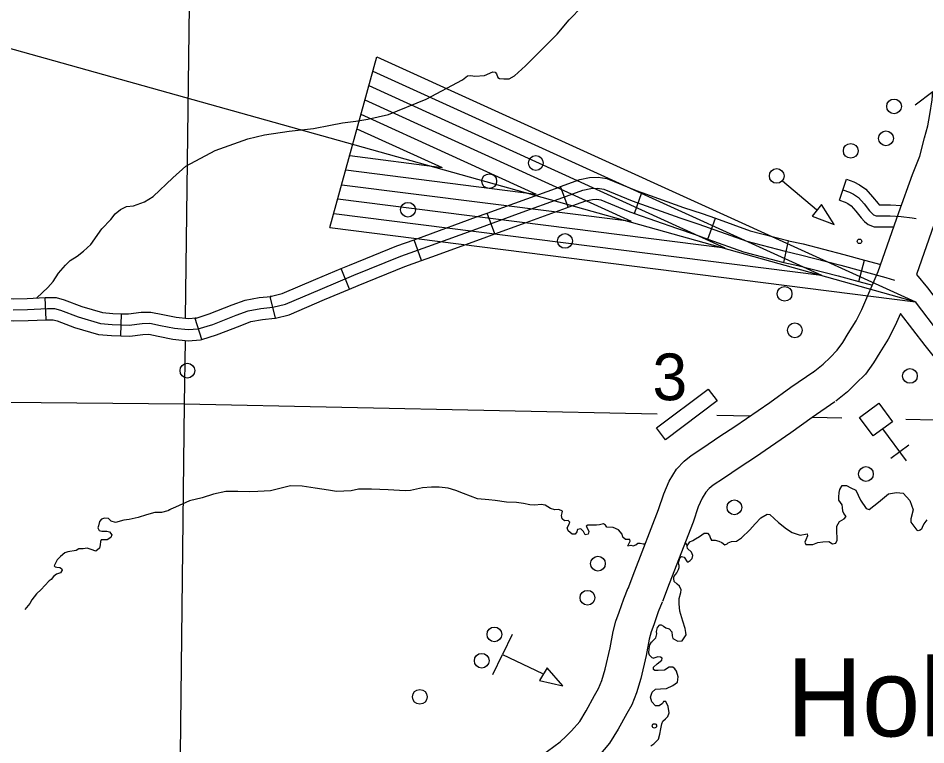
# Model space of a CAD drawing. Extents: x 1369979 to 1371646, y 379997 to 381064.
# Drawn here: x 1370658.6 to 1370730.7, y 380459 to 380516.7 of the extents above; entities that cross this region are included whole.
import ezdxf

# ---------------------------------------------------------------- set-up
doc = ezdxf.new("R2010")
doc.units = 0
for name, color, linetype in [('Default', 7, 'Continuous'), ('R_Border Notes', 7, 'Continuous'), ('R_Draft', 7, 'Continuous')]:
    doc.layers.add(name, color=color, linetype=linetype)

msp = doc.modelspace()

# ---------------------------------------------------------------- linework, layer by layer
at = {"layer": 'Default'}
for p, q in [((1370478.05, 380564.69), (1370729.894, 380494.17)), ((1370683.39, 380500.064), (1370687.104, 380513.627)), ((1370687.104, 380513.627), (1370729.871, 380494.168)), ((1370686.794, 380512.494), (1370722.417, 380496.285)), ((1370686.478, 380511.341), (1370714.748, 380498.463)), ((1370686.168, 380510.208), (1370707.314, 380500.575)), ((1370685.854, 380509.062), (1370699.755, 380502.721)), ((1370685.537, 380507.903), (1370692.295, 380504.84)), ((1370684.956, 380505.782), (1370692.295, 380504.84)), ((1370684.646, 380504.649), (1370699.755, 380502.721)), ((1370684.325, 380503.476), (1370707.314, 380500.575)), ((1370684.015, 380502.343), (1370714.748, 380498.463)), ((1370683.699, 380501.19), (1370722.417, 380496.285)), ((1370683.39, 380500.064), (1370729.871, 380494.168))]:
    msp.add_line(p, q, dxfattribs=at)
at = {"layer": 'R_Border Notes'}
for p, q in [((1370702.302, 380501.677), (1370701.693, 380503.326)), ((1370722.004, 380501.488), (1370719.312, 380503.749)), ((1370723.838, 380502.234), (1370724.394, 380503.902)), ((1370707.561, 380501.198), (1370708.151, 380502.854)), ((1370696.479, 380499.566), (1370695.882, 380501.22)), ((1370713.398, 380499.15), (1370713.99, 380500.805)), ((1370690.665, 380497.456), (1370690.064, 380499.108)), ((1370719.415, 380497.31), (1370719.795, 380499.027)), ((1370684.954, 380495.19), (1370684.274, 380496.811)), ((1370725.369, 380495.788), (1370725.828, 380497.485)), ((1370660.865, 380492.752), (1370660.793, 380494.509)), ((1370679.075, 380492.888), (1370678.655, 380494.595)), ((1370666.797, 380491.474), (1370666.848, 380493.231)), ((1370673.22, 380491.188), (1370672.686, 380492.863)), ((1370729.156, 380481.555), (1370727.276, 380484.09)), ((1370729.338, 380482.785), (1370727.926, 380481.738)), ((1370697.844, 380467.763), (1370697.085, 380466.178)), ((1370696.326, 380464.592), (1370697.085, 380466.178)), ((1370697.085, 380466.178), (1370700.256, 380464.66))]:
    msp.add_line(p, q, dxfattribs=at)
for points in [[(1370672.222, 380548.357), (1370672.203, 380517.695), (1370671.906, 380492.875)], [(1370702.369, 380516.557), (1370703.407, 380517.62)], [(1370686.398, 380508.676), (1370688.042, 380509.043), (1370691.022, 380510.276), (1370693.902, 380511.811), (1370694.303, 380512.112), (1370694.561, 380512.14), (1370694.89, 380512.083), (1370695.65, 380512.155), (1370696.323, 380512.427), (1370696.495, 380512.413), (1370696.609, 380512.27), (1370696.71, 380511.997), (1370696.853, 380511.897), (1370697.197, 380511.868), (1370697.627, 380511.868), (1370698.042, 380512.126), (1370698.916, 380512.9), (1370701.437, 380515.424), (1370702.369, 380516.557)], [(1370721.739, 380488.601), (1370722.54, 380489.227), (1370723.088, 380489.761), (1370723.66, 380490.334), (1370724.101, 380490.939), (1370724.528, 380491.662), (1370725.153, 380492.669), (1370725.619, 380493.552), (1370726.92, 380496.593), (1370728.556, 380501.271), (1370729.633, 380504.281), (1370730.208, 380505.75), (1370730.596, 380507.186), (1370730.844, 380508.157), (1370731.004, 380509.044), (1370731.183, 380510.211), (1370731.249, 380510.88)], [(1370729.845, 380509.822), (1370731.249, 380510.88)], [(1370734.15, 380510.473), (1370734.091, 380509.846), (1370733.894, 380508.562), (1370733.708, 380507.533), (1370733.429, 380506.441), (1370732.995, 380504.831), (1370732.377, 380503.253), (1370731.318, 380500.294), (1370729.941, 380496.355)], [(1370671.948, 380504.943), (1370674.278, 380506.195), (1370676.871, 380507.127), (1370678.189, 380507.443), (1370680.151, 380507.715), (1370682.071, 380507.93), (1370683.446, 380508.203), (1370684.392, 380508.389), (1370685.438, 380508.518), (1370686.398, 380508.676)], [(1370664.415, 380498.714), (1370665.272, 380499.967), (1370665.988, 380500.713), (1370666.332, 380501.158), (1370666.776, 380501.516), (1370667.249, 380501.731), (1370667.808, 380501.803), (1370668.667, 380502.118), (1370669.355, 380502.534), (1370670.917, 380504.026), (1370671.948, 380504.943)], [(1370701.693, 380503.326), (1370703.225, 380503.892), (1370704, 380504.048), (1370704.676, 380504.082), (1370705.376, 380503.974), (1370707.692, 380503.017), (1370708.151, 380502.854)], [(1370695.882, 380501.22), (1370698.064, 380502.007), (1370701.575, 380503.283), (1370701.693, 380503.326)], [(1370724.394, 380503.902), (1370724.988, 380503.704), (1370725.418, 380503.47), (1370725.931, 380503.117), (1370726.471, 380502.512), (1370726.901, 380501.975), (1370726.978, 380501.887), (1370727.069, 380501.887), (1370727.898, 380501.887), (1370728.758, 380501.833)], [(1370658.234, 380493.546), (1370659.393, 380493.572), (1370660.98, 380493.637), (1370661.527, 380493.637), (1370662.009, 380493.506), (1370663.401, 380492.972), (1370665.184, 380492.451), (1370666.108, 380492.373), (1370667.449, 380492.334), (1370668.477, 380492.464), (1370669.089, 380492.477), (1370669.935, 380492.308), (1370671.054, 380492.074), (1370672.147, 380491.969), (1370672.941, 380492.021), (1370674.087, 380492.386), (1370675.948, 380493.103), (1370676.885, 380493.454), (1370677.9, 380493.637), (1370678.863, 380493.741), (1370679.869, 380493.988), (1370682.615, 380495.161), (1370685.283, 380496.281), (1370689.019, 380497.792), (1370691.166, 380498.574), (1370695.331, 380500.086), (1370698.363, 380501.181), (1370701.877, 380502.457), (1370703.465, 380503.044)], [(1370703.465, 380503.044), (1370704.11, 380503.174), (1370704.63, 380503.2), (1370705.138, 380503.122), (1370707.376, 380502.197), (1370711.177, 380500.842), (1370712.66, 380500.347), (1370716.487, 380498.979), (1370719.532, 380498.185), (1370720.751, 380497.915), (1370723.952, 380497.081), (1370727.518, 380496.117), (1370728.216, 380495.898)], [(1370708.151, 380502.854), (1370711.463, 380501.673), (1370712.947, 380501.178), (1370713.99, 380500.805)], [(1370724.116, 380503.068), (1370724.637, 380502.894), (1370724.958, 380502.72), (1370725.345, 380502.453), (1370725.8, 380501.945), (1370726.227, 380501.41), (1370726.428, 380501.182), (1370726.548, 380501.089), (1370726.748, 380501.008), (1370727.069, 380501.008), (1370727.871, 380501.008), (1370728.726, 380500.955), (1370729.608, 380500.848), (1370729.937, 380500.782)], [(1370702.302, 380501.677), (1370703.706, 380502.196), (1370704.219, 380502.299), (1370704.585, 380502.318), (1370704.9, 380502.269), (1370707.061, 380501.376), (1370707.561, 380501.198)], [(1370723.838, 380502.234), (1370724.286, 380502.085), (1370724.497, 380501.97), (1370724.76, 380501.789), (1370725.128, 380501.377), (1370725.554, 380500.844), (1370725.823, 380500.539), (1370726.106, 380500.319), (1370726.579, 380500.129), (1370727.069, 380500.129), (1370728.157, 380500.129)], [(1370690.064, 380499.108), (1370690.866, 380499.4), (1370695.032, 380500.913), (1370695.882, 380501.22)], [(1370696.479, 380499.566), (1370698.663, 380500.354), (1370702.18, 380501.632), (1370702.302, 380501.677)], [(1370707.561, 380501.198), (1370710.89, 380500.011), (1370712.373, 380499.516), (1370713.398, 380499.15)], [(1370713.99, 380500.805), (1370716.746, 380499.82), (1370719.738, 380499.039), (1370719.795, 380499.027)], [(1370684.274, 380496.811), (1370684.948, 380497.094), (1370688.703, 380498.613), (1370690.064, 380499.108)], [(1370690.665, 380497.456), (1370691.466, 380497.748), (1370695.63, 380499.26), (1370696.479, 380499.566)], [(1370713.398, 380499.15), (1370716.227, 380498.139), (1370719.326, 380497.33), (1370719.415, 380497.31)], [(1370719.795, 380499.027), (1370720.956, 380498.769), (1370724.178, 380497.931), (1370725.828, 380497.485)], [(1370660.119, 380494.481), (1370661.006, 380495.301), (1370661.407, 380495.789), (1370661.837, 380496.448), (1370662.395, 380497.094), (1370662.768, 380497.467), (1370663.312, 380497.796), (1370663.828, 380498.198), (1370664.415, 380498.714)], [(1370678.655, 380494.595), (1370679.59, 380494.825), (1370682.273, 380495.97), (1370684.274, 380496.811)], [(1370684.954, 380495.19), (1370685.618, 380495.469), (1370689.334, 380496.972), (1370690.665, 380497.456)], [(1370719.415, 380497.31), (1370720.545, 380497.06), (1370723.727, 380496.232), (1370725.369, 380495.788)], [(1370725.828, 380497.485), (1370727.111, 380497.138)], [(1370729.941, 380496.355), (1370730.814, 380495.289), (1370732.94, 380492.507), (1370734.567, 380490.493), (1370735.521, 380489.608), (1370737.768, 380487.788), (1370738.606, 380487.161), (1370739.233, 380486.747), (1370739.724, 380486.548), (1370740.127, 380486.407), (1370740.452, 380486.351), (1370741.212, 380486.28)], [(1370725.369, 380495.788), (1370726.45, 380495.495)], [(1370654.977, 380495.154), (1370657.024, 380494.582), (1370657.723, 380494.436), (1370658.234, 380494.425), (1370659.365, 380494.45), (1370660.793, 380494.509)], [(1370679.075, 380492.888), (1370680.148, 380493.152), (1370682.958, 380494.352), (1370684.954, 380495.19)], [(1370660.793, 380494.509), (1370660.962, 380494.516), (1370661.644, 380494.516), (1370662.282, 380494.343), (1370663.682, 380493.806), (1370665.346, 380493.32), (1370666.158, 380493.251), (1370666.848, 380493.231)], [(1370672.686, 380492.863), (1370673.795, 380493.216), (1370675.635, 380493.924), (1370676.651, 380494.305), (1370677.775, 380494.507), (1370678.711, 380494.608), (1370678.656, 380494.595)], [(1370654.504, 380493.461), (1370656.607, 380492.874), (1370657.522, 380492.682), (1370658.235, 380492.666), (1370659.421, 380492.693), (1370660.865, 380492.752)], [(1370666.848, 380493.231), (1370667.406, 380493.215), (1370668.412, 380493.342), (1370669.167, 380493.358), (1370670.111, 380493.169), (1370671.186, 380492.944), (1370672.16, 380492.851), (1370672.777, 380492.891), (1370672.687, 380492.863)], [(1370728.679, 380493.257), (1370728.266, 380492.291), (1370727.696, 380491.211), (1370727.034, 380490.144), (1370726.551, 380489.327), (1370725.893, 380488.424), (1370725.147, 380487.677), (1370724.471, 380487.018), (1370723.545, 380486.293)], [(1370741.374, 380483.346), (1370741.138, 380483.345), (1370740.068, 380483.444), (1370739.389, 380483.561), (1370738.689, 380483.806), (1370737.862, 380484.141), (1370736.92, 380484.764), (1370735.968, 380485.476), (1370733.601, 380487.394), (1370732.42, 380488.488), (1370730.636, 380490.696), (1370728.679, 380493.257)], [(1370660.865, 380492.752), (1370660.999, 380492.758), (1370661.41, 380492.758), (1370661.736, 380492.67), (1370663.12, 380492.139), (1370665.022, 380491.583), (1370666.059, 380491.495), (1370666.797, 380491.474)], [(1370673.22, 380491.188), (1370674.378, 380491.557), (1370676.26, 380492.281), (1370677.119, 380492.603), (1370678.025, 380492.766), (1370679.016, 380492.873), (1370679.074, 380492.888)], [(1370666.797, 380491.474), (1370667.492, 380491.454), (1370668.542, 380491.587), (1370669.011, 380491.597), (1370669.758, 380491.447), (1370670.922, 380491.203), (1370672.134, 380491.088), (1370673.105, 380491.151), (1370673.219, 380491.187)], [(1370671.885, 380491.111), (1370671.824, 380486.072)], [(1370707.052, 380471.422), (1370707.587, 380472.822), (1370709.462, 380477.694), (1370709.893, 380478.941), (1370710.309, 380479.928), (1370710.896, 380480.893), (1370711.516, 380481.513), (1370712.065, 380481.965), (1370712.987, 380482.585), (1370714.352, 380483.503), (1370715.532, 380484.268), (1370718.297, 380486.18), (1370719.977, 380487.39), (1370721.811, 380488.653)], [(1370623.576, 380486.521), (1370671.824, 380486.072)], [(1370671.824, 380486.072), (1370671.497, 380458.298)], [(1370671.824, 380486.072), (1370709.375, 380485.271)], [(1370723.473, 380486.24), (1370721.664, 380484.995), (1370719.986, 380483.786), (1370717.163, 380481.834), (1370715.966, 380481.058), (1370714.622, 380480.155), (1370713.818, 380479.613), (1370713.488, 380479.342), (1370713.217, 380479.071), (1370712.925, 380478.59), (1370712.631, 380477.892), (1370712.214, 380476.689), (1370710.322, 380471.774), (1370709.79, 380470.378)], [(1370714.109, 380485.17), (1370716.754, 380485.114)], [(1370721.684, 380485.009), (1370724.019, 380484.959)], [(1370729.103, 380484.85), (1370733.718, 380484.752)], [(1370680.251, 380479.569), (1370678.679, 380479.169), (1370677.657, 380479.109), (1370677.036, 380479.08), (1370676.089, 380479.124), (1370675.112, 380479.109), (1370674.135, 380478.902), (1370673.247, 380478.621), (1370672.241, 380478.369), (1370671.131, 380477.865), (1370670.583, 380477.643)], [(1370690.747, 380479.398), (1370689.79, 380479.183), (1370689.413, 380479.176), (1370688.902, 380479.191), (1370687.999, 380479.235), (1370686.689, 380479.309), (1370685.668, 380479.295), (1370685.069, 380479.161), (1370683.922, 380479.109), (1370683.278, 380479.213), (1370682.227, 380479.383), (1370681.184, 380479.532), (1370680.251, 380479.569)], [(1370714.726, 380474.881), (1370714.921, 380474.958), (1370715.009, 380475.047), (1370715.261, 380475.136), (1370715.675, 380475.181), (1370716.06, 380475.447), (1370716.711, 380476.084), (1370717.154, 380476.543), (1370717.583, 380477.031), (1370718.101, 380477.328), (1370718.308, 380477.283), (1370719.004, 380476.661), (1370719.64, 380476.143), (1370720.069, 380475.847), (1370720.705, 380475.654), (1370721.282, 380475.743), (1370721.312, 380475.595), (1370721.178, 380475.269), (1370721.09, 380475.092), (1370721.178, 380474.899), (1370721.726, 380474.914), (1370722.125, 380475.062), (1370722.525, 380475.121), (1370722.998, 380475.136), (1370723.294, 380474.958), (1370723.545, 380475.003), (1370723.664, 380475.255), (1370723.619, 380476.099), (1370723.634, 380476.35), (1370723.827, 380476.721), (1370724.211, 380476.943), (1370724.359, 380477.135), (1370724.196, 380477.372), (1370724.093, 380477.565), (1370724.078, 380477.846), (1370724.063, 380478.068), (1370723.782, 380478.438), (1370723.782, 380478.66), (1370723.812, 380479.045), (1370723.856, 380479.267), (1370724.063, 380479.593), (1370724.403, 380479.593), (1370724.744, 380479.401), (1370725.128, 380479.223), (1370725.498, 380478.438), (1370725.957, 380477.757), (1370726.194, 380477.683), (1370726.948, 380478.275), (1370727.732, 380478.927), (1370728.353, 380479.031), (1370728.901, 380478.986), (1370729.419, 380478.409), (1370729.684, 380477.65)], [(1370700.146, 380478.079), (1370699.665, 380478.043), (1370699.258, 380478.05), (1370698.762, 380478.161), (1370698.199, 380478.235), (1370697.393, 380478.258), (1370696.505, 380478.406), (1370695.994, 380478.458), (1370695.106, 380478.539), (1370693.996, 380478.961), (1370693.389, 380479.183), (1370692.775, 380479.376), (1370692.057, 380479.45), (1370691.443, 380479.472), (1370690.747, 380479.398)], [(1370707.036, 380474.799), (1370707.217, 380475.176), (1370707.188, 380475.295), (1370706.951, 380475.309), (1370706.847, 380475.295), (1370706.64, 380475.502), (1370706.596, 380475.739), (1370706.285, 380476.065), (1370705.871, 380476.257), (1370705.368, 380476.272), (1370705.265, 380476.435), (1370705.102, 380476.553), (1370704.791, 380476.479), (1370704.554, 380476.435), (1370704.125, 380476.45), (1370703.859, 380476.45), (1370703.726, 380476.376), (1370703.83, 380476.183), (1370703.933, 380475.931), (1370703.889, 380475.724), (1370703.637, 380475.665), (1370703.519, 380475.931), (1370703.297, 380476.154), (1370703.031, 380476.109), (1370703.001, 380475.917), (1370702.868, 380475.724), (1370702.616, 380475.739), (1370702.306, 380476.005), (1370702.232, 380476.228), (1370702.35, 380476.464), (1370702.424, 380476.687), (1370702.291, 380476.805), (1370702.01, 380476.79), (1370701.818, 380476.953), (1370701.758, 380477.205), (1370701.832, 380477.412), (1370701.847, 380477.56), (1370701.566, 380477.679), (1370701.241, 380477.664), (1370700.9, 380477.768), (1370700.479, 380478.028), (1370700.146, 380478.079)], [(1370670.687, 380477.672), (1370670.509, 380477.584), (1370670.021, 380477.45), (1370669.488, 380477.45), (1370668.836, 380477.272), (1370668.156, 380477.05), (1370667.445, 380476.887), (1370667.031, 380476.828)], [(1370729.684, 380477.65), (1370729.515, 380476.943), (1370729.515, 380476.691), (1370729.737, 380476.35), (1370729.988, 380476.039)], [(1370666.365, 380476.65), (1370666.013, 380476.754), (1370665.805, 380476.961), (1370665.495, 380476.991), (1370665.243, 380476.917), (1370665.095, 380476.724), (1370665.006, 380476.398), (1370664.962, 380476.235), (1370665.065, 380476.013), (1370665.287, 380475.969), (1370665.672, 380475.969), (1370665.879, 380475.91), (1370666.072, 380475.687), (1370665.998, 380475.465), (1370665.717, 380475.287), (1370665.421, 380475.273), (1370665.228, 380475.273), (1370665.169, 380475.139), (1370665.154, 380474.887), (1370665.095, 380474.606), (1370664.799, 380474.384), (1370664.429, 380474.517), (1370664.118, 380474.621), (1370663.807, 380474.576), (1370663.452, 380474.562), (1370663.245, 380474.428)], [(1370667.031, 380476.828), (1370666.365, 380476.65)], [(1370730.784, 380476.854), (1370730.547, 380476.543), (1370730.414, 380476.261), (1370730.355, 380476.128), (1370730.252, 380476.039), (1370730.074, 380475.98), (1370729.988, 380476.039)], [(1370711.75, 380474.807), (1370711.962, 380475.106), (1370712.184, 380475.225), (1370712.406, 380475.358), (1370712.731, 380475.536), (1370713.086, 380475.817), (1370713.352, 380475.802), (1370713.53, 380475.625), (1370713.589, 380475.388), (1370713.679, 380475.259)], [(1370713.66, 380475.255), (1370713.679, 380475.259), (1370713.975, 380475.259), (1370714.271, 380475.185), (1370714.508, 380475.066), (1370714.726, 380474.881)], [(1370707.036, 380474.799), (1370707.288, 380474.85), (1370707.45, 380474.813), (1370707.672, 380474.873), (1370707.828, 380475.013), (1370708.027, 380475.021), (1370708.257, 380474.961), (1370708.394, 380474.95)], [(1370711.574, 380475.028), (1370711.607, 380475.021), (1370711.75, 380474.807)], [(1370712.096, 380474.296), (1370711.771, 380474.578), (1370711.756, 380474.756), (1370711.75, 380474.807)], [(1370663.245, 380474.428), (1370662.579, 380474.316), (1370662.342, 380474.242), (1370662.002, 380473.96), (1370661.735, 380473.679), (1370661.528, 380473.279), (1370661.499, 380473.219), (1370661.573, 380473.131), (1370661.706, 380473.116), (1370661.957, 380473.086), (1370662.076, 380472.997), (1370662.135, 380472.879), (1370662.002, 380472.671), (1370661.676, 380472.553), (1370661.439, 380472.375), (1370661.247, 380472.123), (1370661.099, 380472.019), (1370660.744, 380471.649), (1370660.463, 380471.323), (1370660.107, 380470.982), (1370659.723, 380470.523), (1370659.575, 380470.227), (1370659.175, 380469.753)], [(1370711.074, 380473.299), (1370711.061, 380473.467), (1370711.105, 380473.647), (1370711.172, 380473.834), (1370711.308, 380473.961), (1370711.519, 380473.897), (1370711.756, 380473.541), (1370711.83, 380473.526), (1370711.978, 380473.63), (1370712.141, 380473.808), (1370712.2, 380474.045), (1370712.096, 380474.296)], [(1370711.074, 380473.299), (1370711.079, 380473.066), (1370711.028, 380472.884), (1370710.931, 380472.689), (1370710.795, 380472.528), (1370710.723, 380472.426), (1370710.673, 380472.295), (1370710.664, 380472.185), (1370710.7, 380472.001)], [(1370708.888, 380467.154), (1370708.96, 380467.21), (1370709.256, 380467.491), (1370709.33, 380467.817), (1370709.3, 380468.009), (1370709.389, 380468.32), (1370709.581, 380468.527), (1370709.685, 380468.542), (1370709.862, 380468.424), (1370710.055, 380468.29), (1370710.306, 380468.202), (1370710.528, 380467.98), (1370710.558, 380467.654), (1370710.617, 380467.446), (1370711.002, 380467.239), (1370711.342, 380467.254), (1370711.519, 380467.491), (1370711.667, 380467.743), (1370711.653, 380467.92), (1370711.579, 380468.246), (1370711.416, 380468.809), (1370711.164, 380469.608), (1370711.105, 380470.201), (1370711.12, 380470.615), (1370711.253, 380471.089), (1370711.268, 380471.296), (1370711.135, 380471.593), (1370710.942, 380471.77), (1370710.7, 380472.001)], [(1370693.412, 380454.704), (1370694.409, 380455.054), (1370695.938, 380455.714), (1370697.508, 380456.463), (1370698.519, 380457.049), (1370699.488, 380457.655), (1370700.079, 380458.045), (1370700.669, 380458.487), (1370701.655, 380459.235), (1370702.152, 380459.679), (1370702.573, 380460.114), (1370703.221, 380460.864), (1370703.735, 380461.703), (1370704.397, 380462.921), (1370704.704, 380463.465), (1370704.971, 380464.113), (1370705.235, 380465.005), (1370705.627, 380466.694), (1370705.88, 380468.006), (1370706.082, 380468.833), (1370706.34, 380469.524), (1370706.71, 380470.601), (1370707.069, 380471.463)], [(1370709.773, 380470.337), (1370709.451, 380469.562), (1370709.098, 380468.534), (1370708.886, 380467.969), (1370708.743, 380467.381), (1370708.493, 380466.086), (1370708.069, 380464.256), (1370707.737, 380463.137), (1370707.345, 380462.183), (1370706.96, 380461.502), (1370706.273, 380460.237), (1370705.594, 380459.129), (1370704.735, 380458.136), (1370704.183, 380457.565), (1370703.518, 380456.972), (1370702.433, 380456.149), (1370701.767, 380455.648), (1370701.071, 380455.19), (1370700.031, 380454.539), (1370698.876, 380453.869), (1370697.149, 380453.046), (1370695.476, 380452.324), (1370694.442, 380451.961)], [(1370708.888, 380467.154), (1370708.759, 380466.931), (1370708.699, 380466.626), (1370708.682, 380466.312), (1370708.742, 380466.16), (1370708.835, 380466.05), (1370708.937, 380465.939), (1370709.091, 380465.892)], [(1370710.055, 380462.452), (1370709.877, 380462.449), (1370709.788, 380462.271), (1370709.522, 380462.108), (1370709.226, 380462.108), (1370708.93, 380462.404), (1370708.842, 380462.789), (1370708.96, 380463.174), (1370709.241, 380463.411), (1370709.641, 380463.441), (1370710.099, 380463.471), (1370710.602, 380463.722), (1370710.972, 380463.989), (1370711.031, 380464.403), (1370710.913, 380464.848), (1370710.78, 380465.025), (1370710.617, 380465.159), (1370710.321, 380465.159), (1370709.951, 380464.936), (1370709.433, 380464.892), (1370709.182, 380464.892), (1370709.064, 380464.996), (1370709.064, 380465.159), (1370709.359, 380465.44), (1370709.729, 380465.721), (1370709.759, 380465.884), (1370709.626, 380465.973), (1370709.419, 380465.988), (1370709.091, 380465.892)], [(1370708.871, 380458.913), (1370709.108, 380459.09), (1370709.463, 380459.446), (1370709.581, 380459.846), (1370709.655, 380460.275), (1370709.729, 380460.675), (1370709.803, 380460.882), (1370710.04, 380461.06), (1370710.218, 380461.252), (1370710.321, 380461.548), (1370710.232, 380462.052), (1370710.055, 380462.452)]]:
    msp.add_lwpolyline(points, dxfattribs=at)
for points in [[(1370722.422, 380501.902), (1370721.663, 380500.978), (1370723.427, 380500.301)], [(1370710.028, 380483.229), (1370709.324, 380484.167), (1370713.424, 380487.245), (1370714.128, 380486.308)], [(1370726.952, 380486.125), (1370728.041, 380484.656), (1370726.517, 380483.527), (1370725.428, 380484.996)], [(1370700.646, 380465.122), (1370700.025, 380464.1), (1370701.867, 380463.68)]]:
    msp.add_lwpolyline(points, close=True, dxfattribs=at)
for centre, radius in [((1370728.174, 380509.689), 0.586), ((1370727.53, 380507.153), 0.586), ((1370724.733, 380506.164), 0.586), ((1370699.734, 380505.195), 0.586), ((1370718.858, 380504.171), 0.586), ((1370696.033, 380503.752), 0.586), ((1370689.584, 380501.484), 0.586), ((1370702.052, 380499.009), 0.586), ((1370725.426, 380498.979), 0.176), ((1370719.482, 380494.808), 0.586), ((1370720.292, 380491.913), 0.586), ((1370672.076, 380488.712), 0.586), ((1370729.431, 380488.293), 0.586), ((1370725.939, 380480.501), 0.586), ((1370715.5, 380477.857), 0.586), ((1370704.661, 380473.388), 0.586), ((1370703.832, 380470.68), 0.586), ((1370696.444, 380467.77), 0.586), ((1370695.442, 380465.676), 0.586), ((1370690.524, 380462.814), 0.586), ((1370709.145, 380460.506), 0.176)]:
    msp.add_circle(centre, radius, dxfattribs=at)
at = {"layer": 'R_Draft'}
msp.add_lwpolyline([(1370741.366, 380484.846), (1370741.203, 380484.846), (1370740.265, 380484.933), (1370739.767, 380485.018), (1370739.219, 380485.21), (1370738.564, 380485.475), (1370737.783, 380485.991), (1370736.89, 380486.659), (1370734.584, 380488.528), (1370733.519, 380489.515), (1370731.816, 380491.623), (1370729.871, 380494.168)], dxfattribs=at)

# ---------------------------------------------------------------- texts
at = {"layer": 'R_Border Notes'}
for s, height, p in [('3', 3.712, (1370708.99, 380486.36)), ('Holly', 6.1875, (1370719.665, 380459.669))]:
    msp.add_text(s, height=height, dxfattribs=at).set_placement(p)

doc.saveas('drawing.dxf')
